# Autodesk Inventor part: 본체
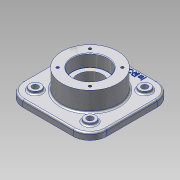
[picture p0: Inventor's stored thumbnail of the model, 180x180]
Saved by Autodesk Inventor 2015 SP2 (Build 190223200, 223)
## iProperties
Created: 2015-07
Part Number: 본체
Material: 일반
Document SubType Name: Modeling
Designer: AMC
Density: 1 g/cm^3
Appearance: 알루미늄 - 평지
Author: AMC
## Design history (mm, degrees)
sketch "스케치1"
  geometry: L1 (-75, -75)-(75, -75); L2 (75, -75)-(75, 75); L3 (75, 75)-(-75, 75); L4 (-75, 75)-(-75, -75); L5 (-75, -75)-(75, 75); L6 (75, -75)-(-75, 75); 1 further point
  constraints: 12 end point, 2 midpoint, 2 parallel, 1 horizontal, 1 perpendicular
  dimensions: "d0" = 150 distance of L3.end L2.end; "d1" = 150 distance of L2.end L1.end
extrude "돌출1" new body sketch "스케치1" distance "d2" = 12; taper "d3" = 0 deg
sketch "스케치2"
  geometry: C1 r 50 at (0, 0); 1 further point
  constraints: 1 centre point, 1 coincident
  dimensions: "d4" = 100 diameter of C1
extrude "돌출2" join sketch "스케치2" distance "d5" = 47; taper "d7" = 0 deg; dims "d6" = 23, "d8" = 0
fillet "모깎기1" dims "d9" = 30
hole "구멍1" diameter "d12" = 45; stored, may be unused: countersink angle "d16" = 90 deg, drill point angle "d18" = 0 deg; dims "d10" = 10, "d11" = 10, "d13" = 6, "d14" = 62, "d15" = 22, "d17" = 8
hole "구멍2" diameter "d21" = 62; stored, may be unused: countersink angle "d25" = 90 deg, drill point angle "d27" = 0 deg; dims "d19" = 10, "d20" = 10, "d22" = 6, "d23" = 62, "d24" = 22, "d26" = 22
sketch "스케치3" dims "d14" = 62
  geometry: L1 (-45, -75)-(45, -75) reference; L2 (-75, 45)-(-75, -45) reference; C1 r 10 at (49, 49); C2 r 10 at (-49, 49); C3 r 10 at (-49, -49); C4 r 10 at (49, -49); 1 further point
  constraints: 4 centre point, 2 horizontal alignment, 2 vertical alignment
  dimensions: "d29" = 20 diameter of C1; "d31" = 20 diameter of C2; "d102" = 20 diameter of C3; "d103" = 20 diameter of C4; "d104" = 98 distance of C1.centre C2.centre; "d105" = 98 distance of C4.centre C1.centre; "d107" = 26 distance from line of L2 C3.centre; "d108" = 26 distance from line of L1 C3.centre
extrude "돌출3" join sketch "스케치3" distance "d32" = 5; taper "d33" = 0 deg
hole "구멍3" diameter "d36" = 11; stored, may be unused: countersink angle "d40" = 90 deg, drill point angle "d42" = 0 deg; dims "d34" = 10, "d35" = 10, "d37" = 6, "d38" = 62, "d39" = 22, "d41" = 22
hole "구멍4" diameter "d45" = 11; stored, may be unused: countersink angle "d49" = 90 deg, drill point angle "d51" = 0 deg; dims "d43" = 10, "d44" = 10, "d46" = 6, "d47" = 62, "d48" = 22, "d50" = 22
hole "구멍5" diameter "d54" = 11; stored, may be unused: countersink angle "d58" = 90 deg, drill point angle "d60" = 0 deg; dims "d52" = 10, "d53" = 10, "d55" = 6, "d56" = 62, "d57" = 22, "d59" = 22
hole "구멍6" diameter "d63" = 11; stored, may be unused: countersink angle "d67" = 90 deg, drill point angle "d69" = 0 deg; dims "d61" = 10, "d62" = 10, "d64" = 6, "d65" = 62, "d66" = 22, "d68" = 22
fillet "모깎기2" dims "d70" = 3
sketch "스케치4"
  geometry: L1 (0, 0)-(41, 0); L2 (0, 0)-(28.991, 28.991); A1 r 41 centre (0, 0) between (41, 0) and (28.991, 28.991); 1 further point
  constraints: 4 end point, 2 point on circle, 1 centre point, 1 coincident, 1 horizontal
  dimensions: "d71" = 82 diameter of A1; "d72" = 45 deg angle of L1 L2
hole "구멍7" sketch "스케치4" at (28.991, 28.991) diameter "d73" = 4.917; stored, may be unused: countersink angle "d77" = 90 deg, drill point angle "d79" = 118 deg; dims "d74" = 10, "d75" = 62, "d76" = 22, "d78" = 13
sketch "스케치5"
  geometry: L1 (0, 0)-(41, 0); L2 (0, 0)-(28.991, 28.991); A1 r 41 centre (0, 0) between (41, 0) and (28.991, 28.991); 1 further point
  constraints: 4 end point, 2 point on circle, 1 centre point, 1 coincident, 1 horizontal
  dimensions: "d83" = 82 diameter of A1; "d84" = 45 deg angle of L1 L2
hole "구멍8" sketch "스케치5" at (28.991, 28.991) diameter "d85" = 4.917; stored, may be unused: countersink angle "d89" = 90 deg, drill point angle "d91" = 118 deg; dims "d86" = 10, "d87" = 62, "d88" = 22, "d90" = 13
fillet "모깎기3" dims "d95" = 0.3
chamfer "모따기1" distance "d96" = 1; stored, may be unused: second distance "d97" = 2, angle "d98" = 45 deg
sketch "스케치6"
  geometry: 2 further points
  constraints: 1 vertical alignment, 1 other
  dimensions: "d99" = 65 distance of point (0, 0) point (0, 65)
feature "엠보싱1" sketch "스케치6" dims "d0" = 150, "d1" = 150, "d100" = 1, "d101" = 0
hole "구멍9" diameter "d111" = 11; stored, may be unused: countersink angle "d115" = 90 deg, drill point angle "d117" = 118 deg; dims "d109" = 10, "d110" = 10, "d112" = 6, "d113" = 4, "d114" = 2, "d116" = 8
hole "구멍10" diameter "d120" = 11; stored, may be unused: countersink angle "d124" = 90 deg, drill point angle "d126" = 118 deg; dims "d118" = 10, "d119" = 10, "d121" = 6, "d122" = 4, "d123" = 2, "d125" = 8
fillet "모깎기4" dims "d127" = 3
node "솔리드1"
pattern_circular "원형 패턴1" dims angle "d81" = 360 deg
pattern_circular "원형 패턴2" dims angle "d93" = 360 deg
